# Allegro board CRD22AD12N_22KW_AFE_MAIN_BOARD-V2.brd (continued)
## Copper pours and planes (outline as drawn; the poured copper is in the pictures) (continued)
PFC_G_LB on BOTTOM (solid shape): 353.31,159 353.31,157.73 353.19,157.61 351.41,157.61 351.15,157.35 351.15,154.43 351.41,154.18 351.41,149.61 351.15,149.35 349.38,149.35 349,149.73 349,154.13 349.25,154.38 349.25,159 349.38,159.13 353.19,159.13
PFC_G_LC on BOTTOM (solid shape): 353.31,109.98 353.31,108.84 353.19,108.71 351.41,108.71 351.15,108.46 351.15,105.54 351.41,105.28 351.41,100.71 351.15,100.46 349.38,100.46 349,100.84 349,105.23 349.25,105.49 349.25,110.11 349.38,110.24 353.06,110.24
VP+5V on BOTTOM (solid shape): outline of 521 points within 245.24,2.16 259.08,20.57
VP+15V on TOP (solid shape): outline of 528 points within 360.55,33.91 364.52,161.04
VP+15V on BOTTOM (solid shape): 364.49,161.29 364.49,158.75 364.36,158.62 362.2,158.62 362.08,158.5 361.19,158.5 360.3,159.38 358.52,159.38 358.39,159.51 358.39,161.16 358.65,161.42 364.36,161.42
VP+15V on BOTTOM (solid shape): 364.49,135.25 364.49,132.72 364.36,132.59 362.2,132.59 362.08,132.46 361.19,132.46 360.3,133.35 358.52,133.35 358.39,133.48 358.39,135.13 358.65,135.38 364.36,135.38
VP+15V on BOTTOM (solid shape): 364.49,112.39 364.49,109.86 364.36,109.73 362.2,109.73 362.08,109.6 361.19,109.6 360.3,110.49 358.52,110.49 358.39,110.62 358.39,112.27 358.65,112.52 364.36,112.52
VP+15V on BOTTOM (solid shape): 364.49,86.36 364.49,83.82 364.36,83.69 362.2,83.69 362.08,83.57 361.19,83.57 360.3,84.45 358.52,84.45 358.39,84.58 358.39,86.23 358.65,86.49 364.36,86.49
VP+15V on BOTTOM (solid shape): 364.49,63.5 364.49,60.96 364.36,60.83 362.2,60.83 362.08,60.71 361.19,60.71 360.3,61.59 358.52,61.59 358.39,61.72 358.39,63.37 358.65,63.63 364.36,63.63
VP+15V on BOTTOM (solid shape): 364.49,37.47 364.49,34.92 364.36,34.8 362.2,34.8 362.08,34.67 361.19,34.67 360.3,35.56 358.52,35.56 358.39,35.69 358.39,37.34 358.65,37.59 364.36,37.59
VP+15V_PFCHA on BOTTOM (solid shape): 347.85,37.97 347.85,30.81 348.36,30.3 348.36,25.4 348.23,25.27 346.46,25.27 346.2,25.53 346.2,37.97 346.46,38.23 347.6,38.23
VP+15V_PFCHB on BOTTOM (solid shape): 347.85,135.76 347.85,128.6 348.36,128.09 348.36,123.19 348.23,123.06 346.46,123.06 346.2,123.32 346.2,135.89 346.33,136.02 347.6,136.02
VP+15V_PFCHC on BOTTOM (solid shape): 347.85,87 347.85,79.71 348.36,79.2 348.36,74.3 348.23,74.17 346.46,74.17 346.2,74.42 346.2,87 346.33,87.12 347.73,87.12
VP+15V_PFCLA on BOTTOM (solid shape): 347.85,64.01 347.85,56.85 348.36,56.34 348.36,51.44 348.23,51.31 346.46,51.31 346.2,51.56 346.2,64.01 346.46,64.26 347.6,64.26
VP+15V_PFCLB on BOTTOM (solid shape): 347.85,161.93 347.85,154.64 348.36,154.13 348.36,149.22 348.23,149.1 346.46,149.1 346.2,149.35 346.2,161.8 346.46,162.05 347.73,162.05
VP+15V_PFCLC on BOTTOM (solid shape): 347.85,112.9 347.85,105.74 348.36,105.23 348.36,100.33 348.23,100.2 346.46,100.2 346.2,100.46 346.2,112.9 346.46,113.16 347.6,113.16
VPFC on TOP (solid shape): 235.46,130.81 235.46,119.89 234.19,118.62 137.53,118.62 129.95,120.72 124.8,114.76 119.97,109.94 112.61,109.94 110.06,110.59 107.51,109.94 90.11,109.94 87.56,110.59 85.01,109.94 82.89,109.94 82.17,109.22 46.99,109.22 45.72,110.49 45.72,119.19 59.25,132.72 233.55,132.72
VPFC on BOTTOM (solid shape): 71.63,130.56 71.63,125.48 72.39,124.71 76.45,124.71 77.09,124.08 77.09,110.87 75.82,109.6 47.88,109.6 46.74,110.74 46.74,114.94 62.99,131.19 70.99,131.19
VPFC on GND02 (solid shape): outline of 674 points within 45.72,109.22 236.35,151.26
VPFC on POWER03 (solid shape): outline of 543 points within 45.72,109.22 235.2,151.26
VS+5V on TOP (solid shape): 263.14,12.57 263.14,10.29 262.64,9.78 254.38,9.78 254.13,10.03 254.13,12.06 254.63,12.57 261.49,12.57 261.75,12.83 262.89,12.83
VS+15V on TOP (solid shape): outline of 85 points within 265.56,6.35 272.42,12.95
N17453218 on BOTTOM (solid shape): 364.49,59.69 364.49,51.69 364.24,51.44 361.95,51.44 361.7,51.69 361.7,55.37 362.08,55.75 362.08,58.04 362.58,58.55 362.58,59.56 362.84,59.82 364.36,59.82
N17751858 on BOTTOM (solid shape): 347.48,42.16 347.48,39.37 347.35,39.24 344.43,39.24 344.18,39.5 344.18,40.13 342.4,41.91 342.4,42.93 342.65,43.18 346.46,43.18
N17896613 on TOP (solid shape): outline of 474 points within 21.78,6.48 83.19,47.24
N17896613 on BOTTOM (solid shape): 34.67,46.74 34.67,42.32 34.67,42.32 34.67,27.18 35.78,26.07 35.78,20.77 35.81,20.77 35.81,20.7 37.72,18.8 37.72,14.22 38.73,13.21 43.69,13.21 43.69,15.54 44.48,16.33 44.48,20.69 45.5,21.72 45.5,25.66 46.61,26.76 46.61,28.35 51.28,33.02 80.77,33.02 83.19,30.61 83.19,26.8 79.99,23.6 73.53,23.6 73.52,23.61 62.5,23.61 62.48,23.62 52.58,23.62 49.66,20.7 49.66,19.72 49.61,19.05 49.66,18.39 49.66,14.61 48.39,13.34 48.39,12.09 48.36,11.93 48.35,11.76 48.34,11.28 48.38,10.79 48.34,10.14 48.39,9.5 48.39,5.71 47.75,5.08 32.64,5.08 32,5.71 32,16.43 31.96,16.47 31.96,17.34 31.97,17.36 30.94,23.58 24.71,24.47 24.69,24.47 22.55,24.47 22.12,25.08 21.59,25.6 21.59,26.91 23.09,30.06 21.59,33.22 21.59,35.56 26.54,40.51 26.54,46.99 27.18,47.62 33.78,47.62
N17896948 on BOTTOM (solid shape): 68.01,81.72 68.01,63.58 67.86,63.35 67.71,63.1 66.6,61.18 65.28,59.86 65.28,57 64.96,56.67 64.96,56.61 64.45,56.1 64.45,55.72 63.4,54.67 63.4,43.59 57.47,37.66 50.16,37.66 42.55,30.04 42.55,29.21 41.97,28.64 39.43,28.64 38.73,29.34 38.73,40.64 39.37,41.27 43.05,41.27 53.98,52.2 53.98,55.85 62.61,64.48 62.61,68.81 62.61,68.81 62.67,69.68 62.61,70.55 62.61,70.55 62.61,74.58 53.12,84.07 39.5,84.07 39.12,84.45 39.12,88.27 39.75,88.9 60.83,88.9
N17898200 on TOP (solid shape): outline of 414 points within 21.34,48.9 58.93,76.2
N17898200 on BOTTOM (solid shape): 58.55,72.9 58.55,66.17 55.63,63.25 43.85,63.25 43.47,63.63 37.31,63.63 36.16,62.48 35.05,62.48 33.27,60.71 33.27,54.61 32.26,53.59 28.96,53.59 26.42,56.13 22.8,56.13 22.72,56.18 22.71,56.28 22.95,59.07 21.34,61.35 21.34,62.28 23.09,65.62 21.34,68.97 21.34,70.48 21.72,70.87 38.28,70.87 38.68,70.46 43.03,70.46 46.61,74.04 57.4,74.04
N17898311 on BOTTOM (solid shape): 42.55,58.8 43.81,58.8 44.07,58.55 44.15,58.55 44.15,55.14 41.81,52.81 41.78,52.83 39.12,52.83 38.73,53.21 38.73,59.31 38.99,59.56 41.78,59.56
N17898311 on POWER03 (solid shape): outline of 1396 points within 20.95,18.54 105.54,82.42
N17908016 on TOP (solid shape): outline of 440 points within 75.69,24.79 150.62,50.15
N17908016 on BOTTOM (solid shape): 93.22,43.81 93.22,33.53 92.84,33.15 87.76,33.15 82.55,38.35 75.06,38.35 74.68,38.73 74.68,48.01 75.56,48.9 88.14,48.9
N17908016 on GND02 (solid shape): outline of 95 points within 75.44,30.35 146.05,50.42
N17908018 on BOTTOM (solid shape): 96.12,68.97 96.22,68.33 96.39,67.71 96.39,54.61 95.31,53.53 84.45,53.53 83.38,54.61 83.38,60.77 84.84,62.23 85.83,62.23 88.34,64.74 88.34,66.88 88.29,66.93 88.29,69.6 88.8,70.1 94.99,70.1
N17908018 on GND02 (solid shape): outline of 145 points within 78.64,54.48 169.42,107.31
N17908020 on BOTTOM (solid shape): 93.09,106.43 93.09,92.2 92.33,91.44 85.98,91.44 85.09,92.33 85.09,105.92 85.03,105.98 85.85,106.81 92.71,106.81
N17908020 on POWER03 (solid shape): outline of 366 points within 86.11,32.51 122.58,107.7
N17908062 on TOP (solid shape): 122.3,92.2 122.3,87.12 109.35,74.17 106.92,74.17 102.43,76.03 97.94,74.17 83.8,74.17 83.14,74.22 82.47,74.17 82.47,74.17 81.66,74.17 81.32,73.82 81.31,73.82 79.29,71.93 78.81,69.22 78.77,68.58 78.81,67.94 78.8,66.74 79.12,65.58 79.12,55.75 78.11,54.74 64.9,54.74 62.99,56.64 62.99,82.93 67.18,87.12 102.49,87.12 109.6,94.23 120.27,94.23
N17908062 on BOTTOM (solid shape): 122.3,93.54 122.3,88.77 119.13,85.6 106.68,85.6 104.78,87.5 104.78,93.73 105.85,94.81 121.03,94.81
N17908062 on BOTTOM (solid shape): 78.36,66.55 78.36,56.77 74.04,52.45 68.83,52.45 68.51,52.77 68.51,54.41 69.02,54.92 69.02,54.99 69.34,55.31 69.34,58.18 69.85,58.68 71.23,61.07 71.28,61.16 71.34,61.24 72.08,62.29 72.08,66.29 73.22,67.44 77.47,67.44
N17908062 on GND02 (solid shape): 85.61,94.11 87.56,90.7 89.51,94.11 119,94.11 121.41,91.69 121.41,84.45 119.38,82.42 103.93,82.42 94.4,72.9 85.22,72.9 85.18,72.94 82,72.94 79.17,70.1 79.17,62.18 71.48,54.48 68.16,54.48 66.55,56.09 66.55,89.28 71.37,94.11
N17916039 on TOP (solid shape): 341.88,27.81 341.88,20.07 339.6,17.78 323.98,17.78 322.71,19.05 322.71,30.1 324.1,31.5 338.2,31.5
N17916039 on TOP (solid shape): 319.91,179.45 319.91,168.91 319.4,168.4 313.82,168.4 313.06,169.16 313.06,179.58 313.69,180.21 319.15,180.21
N17916039 on TOP (solid shape): 337.57,79.76 337.57,77.22 337.44,77.09 328.93,77.09 327.53,75.69 327.53,72.64 327.15,72.26 316.23,72.26 315.98,72.52 315.98,79.12 317.25,80.39 336.93,80.39
N17916039 on TOP (solid shape): 337.33,128.27 337.33,126.75 337.31,126.75 336.68,126.11 330.33,126.11 327.53,123.32 327.53,121.28 327.28,121.03 316.74,121.03 316.23,121.54 316.23,128.14 316.74,128.65 336.95,128.65
N17916039 on POWER03 (solid shape): outline of 1342 points within 237.24,17.72 341.88,181.61
N17916066 on BOTTOM (solid shape): 337.96,57.01 337.96,46.99 337.08,46.1 331.49,46.1 331.04,45.66 331.04,36.39 331.49,35.94 336.82,35.94 337.2,35.56 337.2,34.16 336.82,33.78 327.75,33.78 323.25,34.41 319.67,31.62 300.48,31.62 299.28,32.83 299.28,37.91 300.36,38.99 315.67,38.99 318.47,41.79 320,42.95 321.16,44.48 328.71,52.03 329.82,53.44 330.45,55.12 332.87,57.53 337.44,57.53
N17916108 on BOTTOM (solid shape): 338.09,154.81 338.09,144.91 337.71,144.53 332.25,144.53 331.11,143.38 331.11,134.11 331.49,133.73 336.82,133.73 337.08,133.48 337.08,131.97 336.8,131.7 327.53,131.7 324.51,132.4 321.56,131.44 301.12,131.44 299.28,133.29 299.28,137.48 300.48,138.68 314.58,138.68 315.01,138.67 315.43,138.68 317.5,138.68 318.31,139.49 320,140.74 321.25,142.43 328.25,149.44 329.57,150.83 330.37,152.57 332.99,155.19 337.71,155.19
N17916243 on BOTTOM (solid shape): 337.46,105.39 337.46,95.12 336.95,94.61 331.49,94.61 331.11,94.23 331.11,85.34 331.61,84.84 336.8,84.84 337.08,84.56 337.08,83.06 336.82,82.8 327.53,82.8 324.09,83.47 320.9,82.04 300.86,82.04 299.34,83.57 299.34,87.5 300.48,88.65 315.09,88.65 316.35,89.9 320,91.84 321.94,95.5 325.94,99.49 329.16,101.38 330.56,104.84 331.89,106.17 336.68,106.17
N17920487 on TOP (solid shape): 219.33,151.76 219.33,138.43 218.06,137.16 58.29,137.16 50.16,145.29 50.16,162.56 50.8,163.19 207.9,163.19
N17920487 on BOTTOM (solid shape): 54.23,163.19 54.23,157.48 54.86,156.84 80.9,156.84 82.8,158.75 82.8,163.19 83.44,163.83 89.79,163.83 91.06,162.56 91.06,156.84 91.69,156.21 116.46,156.21 119,158.75 119,161.93 119.63,162.56 126.62,162.56 127.25,161.93 127.25,157.48 129.16,155.57 154.56,155.57 156.46,157.48 156.46,162.56 157.1,163.19 162.18,163.19 163.45,161.93 163.45,158.12 166.62,154.94 183.13,154.94 191.39,163.19 198.37,163.19 199.01,162.56 199.01,159.38 201.55,156.84 219.33,156.84 220.22,155.96 220.22,137.79 218.5,136.08 216.98,136.08 216.95,136.05 198.25,136.05 190.4,143.89 182.5,143.89 181.23,142.62 181.23,137.67 180.09,136.53 160.78,136.53 154.05,143.26 146.05,143.26 145.03,142.24 145.03,136.53 144.46,135.95 125.03,135.95 117.73,143.26 109.73,143.26 108.84,142.37 108.84,137.16 108.2,136.53 99.31,136.53 92.46,143.38 74.3,143.38 73.28,142.37 73.28,137.79 71.37,135.89 60.58,135.89 49.66,146.81 49.66,163.96 50.16,164.47 52.96,164.47
N17922803 on BOTTOM (solid shape): 347.48,139.95 347.48,137.16 347.35,137.03 344.43,137.03 344.18,137.29 344.18,137.92 342.4,139.7 342.4,140.72 342.65,140.97 346.46,140.97
N17923421 on BOTTOM (solid shape): 347.48,165.99 347.48,163.19 347.35,163.07 344.43,163.07 344.18,163.32 344.18,163.96 342.4,165.74 342.4,166.75 342.65,167 346.46,167
N17924549 on BOTTOM (solid shape): 347.48,68.2 347.48,65.41 347.35,65.28 344.43,65.28 344.18,65.53 344.18,66.17 342.4,67.94 342.4,68.96 342.65,69.22 346.46,69.22
N17925397 on BOTTOM (solid shape): 347.48,91.06 347.48,88.27 347.35,88.14 344.43,88.14 344.18,88.39 344.18,89.03 342.4,90.81 342.4,91.82 342.65,92.08 346.46,92.08
N17925612 on BOTTOM (solid shape): 347.48,117.09 347.48,114.3 347.35,114.17 344.43,114.17 344.18,114.43 344.18,115.06 342.4,116.84 342.4,117.86 342.65,118.11 346.46,118.11
N17927817 on BOTTOM (solid shape): 364.49,33.66 364.49,25.65 364.24,25.4 361.95,25.4 361.7,25.65 361.7,29.34 362.08,29.72 362.08,32 362.58,32.51 362.58,33.53 362.84,33.78 364.36,33.78
N17928860 on BOTTOM (solid shape): 364.49,131.44 364.49,123.44 364.24,123.19 361.95,123.19 361.7,123.44 361.7,127.13 362.08,127.51 362.08,129.79 362.58,130.3 362.58,131.32 362.84,131.57 364.36,131.57
N17929090 on BOTTOM (solid shape): 364.49,157.48 364.49,149.48 364.24,149.22 361.95,149.22 361.7,149.48 361.7,153.16 362.08,153.54 362.08,155.83 362.58,156.34 362.58,157.35 362.84,157.61 364.36,157.61
N17930170 on BOTTOM (solid shape): 364.49,82.55 364.49,74.55 364.24,74.3 361.95,74.3 361.7,74.55 361.7,77.85 362.08,78.23 362.08,80.9 362.58,81.41 362.58,82.42 362.84,82.68 364.36,82.68
N17930400 on BOTTOM (solid shape): 364.49,108.58 364.49,100.58 364.24,100.33 361.95,100.33 361.7,100.58 361.7,104.01 362.08,104.39 362.08,106.93 362.58,107.44 362.58,108.46 362.84,108.71 364.36,108.71
N17951662 on BOTTOM (solid shape): 233.17,27.43 233.17,25.02 233.04,24.89 231.14,24.89 231.01,25.02 231.01,27.3 231.27,27.56 233.04,27.56
N17952680 on BOTTOM (solid shape): 233.17,93.85 233.17,91.44 233.04,91.31 231.14,91.31 231.01,91.44 231.01,93.73 231.27,93.98 233.04,93.98
N17953229 on BOTTOM (solid shape): 233.17,60.83 233.17,58.42 233.04,58.29 231.14,58.29 231.01,58.42 231.01,60.71 231.27,60.96 233.04,60.96
N18031698 on TOP (solid shape): 34.35,115.13 34.35,110.24 33.34,109.22 27.81,109.22 27.69,109.35 27.69,111.63 27.56,111.76 27.18,111.76 27.05,111.63 27.05,109.35 26.92,109.22 22.1,109.22 21.97,109.35 21.97,115.06 23.37,116.46 33.02,116.46
N18031698 on BOTTOM (solid shape): 34.35,115.13 34.35,110.24 33.34,109.22 29.46,109.22 28.32,110.36 28.32,115.32 29.46,116.46 33.02,116.46
N18031715 on TOP (solid shape): 21.21,131.44 21.21,109.35 21.08,109.22 16.38,109.22 16,109.6 16,111.63 15.88,111.76 15.49,111.76 15.37,111.63 15.37,110.11 15.24,109.98 9.27,109.98 8.64,110.62 8.64,131.44 9.02,131.83 20.83,131.83
N18031715 on POWER03 (solid shape): 20.32,127 20.32,115.06 19.43,114.17 9.14,114.17 8.64,114.68 8.64,127.51 9.02,127.89 19.43,127.89
N18060364 on TOP (solid shape): 34.04,160.02 34.04,132.59 33.02,131.57 28.57,131.57 24.26,135.89 9.27,135.89 9.02,136.14 9.02,160.91 9.27,161.16 32.89,161.16
N18060364 on BOTTOM (solid shape): 34.04,160.02 34.04,132.59 33.02,131.57 28.57,131.57 24.26,135.89 9.27,135.89 9.02,136.14 9.02,160.91 9.27,161.16 32.89,161.16
N18060364 on GND02 (solid shape): 34.04,160.02 34.04,132.59 33.02,131.57 28.57,131.57 24.26,135.89 9.27,135.89 9.02,136.14 9.02,160.91 9.27,161.16 32.89,161.16
N18060364 on POWER03 (solid shape): 34.04,160.02 34.04,132.59 33.02,131.57 28.57,131.57 24.26,135.89 9.27,135.89 9.02,136.14 9.02,160.91 9.27,161.16 32.89,161.16
N18156742 on GND02 (solid shape): outline of 442 points within 178.69,22.48 201.04,81.53
N18158495 on TOP (solid shape): 14.1,184.03 14.1,164.34 2.41,164.34 1.27,165.48 1.27,184.28 1.91,184.92 13.21,184.92
N18189276 on TOP (solid shape): 364.49,183.9 364.49,174.37 364.11,173.99 361.82,173.99 361.57,174.24 361.57,178.31 359.41,180.47 359.41,183.77 360.17,184.53 363.86,184.53
N18202622 on TOP (solid shape): 7.11,8.76 7.11,1.78 6.6,1.27 1.4,1.27 1.27,1.4 1.27,8.89 1.65,9.27 6.6,9.27
N179113761 on TOP (solid shape): 188.85,113.98 188.85,109.22 187.83,108.2 175.77,108.2 175.26,108.71 175.26,114.05 175.58,114.36 188.47,114.36
N179113761 on GND02 (solid shape): 191.33,116.9 191.33,109.79 189.61,108.08 175.26,108.08 173.86,109.47 173.86,117.22 175.13,118.49 189.74,118.49

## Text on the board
BOTTOM: ARTWORK BOTTOM
Board Geometry/Soldermask Bottom: SOLDERMASK BOTTOM
Package Geometry/Pastemask Bottom: PASTEMASK BOTTOM
Ref Des/Silkscreen Bottom: SILKSCREEN BOTTOM
TOP: ARTWORK TOP
Board Geometry/Soldermask Top: SOLDERMASK TOP
Package Geometry/Pastemask Top: PASTEMASK TOP
Ref Des/Silkscreen Top: CRD22AD12N_22KW_MAIN_BOARD | Rev B 1820 | T | M | A | B | C | PE | SILKSCREEN TOP | - | +
GND02: GROUND PLANE02 - INT01
POWER03: POWER PLANE03 - INT02
DIMENSION: Board Cut Out | 4 | 4.    This area one net shorted to mechanical pin, please ignore this one | FAB DRAWING
ASSEMBLY_TOP: PRIMARY SIDE
ASSEMBLY_BOTTOM: SECONDARY SIDE
User.6: POWER PLANE02
User.7: GROUND PLANE03
User.18: FIGURE | SIZE | 12.0 | 32.0 | 39.0 | 40.0 | 47.0 | 51.0 | 55.0 | 59.0 | 79.0 | 87.0 | 122.0 | 236.0 | 67.0x53.0 | 177.17x102.36 | 220.0x110.0 | DRILL CHART: TOP to BOTTOM | ALL UNITS ARE IN MILS | TOLERANCE | +0.0/-0.0 | +3.0/-3.0 | +2.99/-2.99 | PLATED | NON-PLATED | QTY | 282 | 4 | 70 | 45 | 18 | 6 | 22 | 20 | 30 | 8 | 3 | 10
